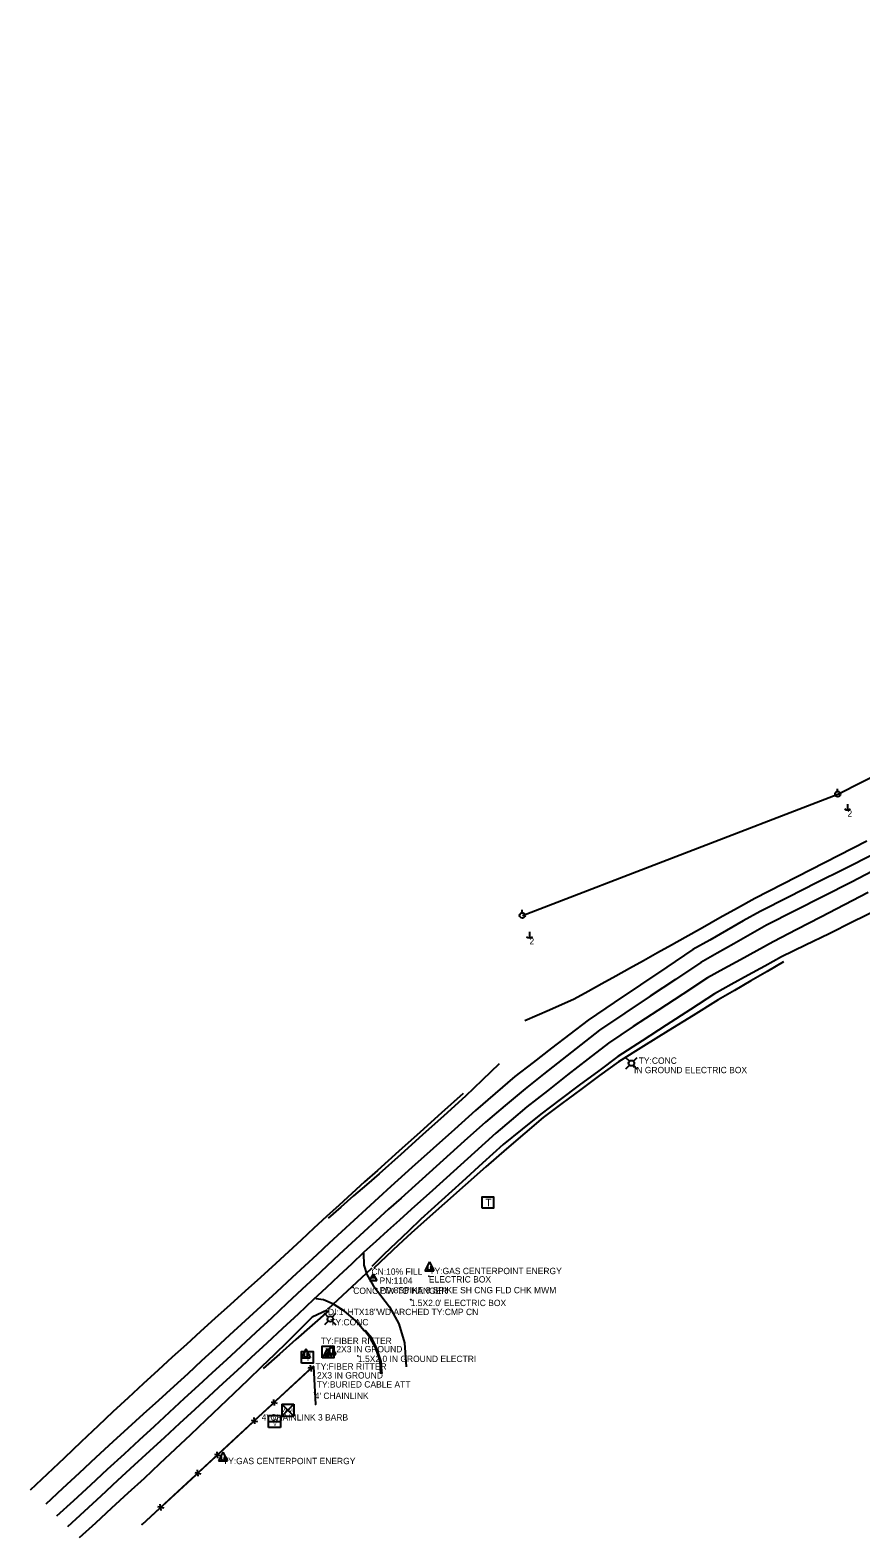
# Model space of a CAD drawing. Extents: x 1707085 to 1720058, y 548761 to 560063.
# Drawn here: x 1710676 to 1711331, y 548761 to 549950 of the extents above; entities that cross this region are included whole.
import ezdxf

# ---------------------------------------------------------------- set-up
doc = ezdxf.new("R2010")
doc.units = 0
for name, color, linetype in [('3', 7, 'Continuous'), ('R_Contours', 7, 'Continuous'), ('R_Draft', 7, 'Continuous'), ('R_Water Annot', 7, 'Continuous'), ('S_CURB', 7, 'Continuous'), ('S_DRG_PT_SYM', 7, 'Continuous'), ('S_DRIVEWAY', 7, 'Continuous'), ('S_EDGE_PAVEMENT', 7, 'Continuous'), ('S_MISC_STRUCTURES_ANNOT', 7, 'Continuous'), ('S_MSC_PT_SYM', 7, 'Continuous'), ('S_PAVEMENT_CROWN', 7, 'Continuous'), ('S_SECONDARY_CTL_ANNOT', 7, 'Continuous'), ('S_SIDE_DRAIN_ANNOT', 7, 'Continuous'), ('S_SURVEY_TEXT_ANNOT', 7, 'Continuous'), ('S_TELEPHONE_UTILITIES', 7, 'Continuous'), ('S_TELEPHONE_UTILITIES_ANNOT', 7, 'Continuous'), ('S_UNDERGROUND_CABLE', 7, 'Continuous'), ('S_UTILITY_POLE', 7, 'Continuous'), ('S_UTILITY_POLE_ANNOT', 7, 'Continuous')]:
    doc.layers.add(name, color=color, linetype=linetype)

msp = doc.modelspace()

# ---------------------------------------------------------------- linework, layer by layer
for points in [[(1711335.9, 549310.1), (1711313.8, 549298.8), (1711291.7, 549287.6), (1711269.7, 549276.4), (1711247.6, 549265.1), (1711233.9, 549257.4), (1711220.2, 549249.7), (1711206.5, 549241.9), (1711192.8, 549234.2), (1711181.9, 549228.2), (1711170.9, 549222.1), (1711160, 549216), (1711149, 549209.9), (1711138.1, 549203.9), (1711127.1, 549197.8), (1711116.2, 549191.7), (1711105.2, 549185.6), (1711085.8, 549177.1), (1711066.4, 549168.6)], [(1711343.8, 549255.7), (1711325, 549246.5), (1711306.3, 549237.3), (1711287.5, 549228.2), (1711268.8, 549219), (1711255.5, 549211.7), (1711242.3, 549204.5), (1711229.1, 549197.2), (1711215.9, 549190), (1711196.9, 549177.6), (1711177.8, 549165.2), (1711158.8, 549152.8), (1711139.8, 549140.5), (1711124.6, 549129.1), (1711109.3, 549117.8), (1711094.1, 549106.5), (1711078.9, 549095.1), (1711064.2, 549083.1), (1711049.4, 549071), (1711033.1, 549056.3), (1711016.9, 549041.6), (1711000.6, 549026.9), (1710984.4, 549012.2), (1710974.7, 549002.9), (1710965, 548993.6), (1710955.3, 548984.3), (1710945.7, 548975)], [(1711270.3, 549215.1), (1711257.4, 549207.6), (1711244.5, 549200.1), (1711231.7, 549192.6), (1711218.8, 549185.1), (1711199.1, 549172.9), (1711179.4, 549160.7), (1711159.8, 549148.5), (1711140.1, 549136.3), (1711125.2, 549125.4), (1711110.4, 549114.4), (1711095.5, 549103.5), (1711080.7, 549092.5), (1711066.3, 549080.1), (1711051.9, 549067.7), (1711035.6, 549053.4), (1711019.3, 549039), (1711003, 549024.6), (1710986.7, 549010.2), (1710976.8, 549001.1), (1710966.9, 548992), (1710957.1, 548982.8), (1710947.2, 548973.7)], [(1711046, 549134.6), (1711032.8, 549121.8), (1711019.5, 549109.1), (1711002.5, 549093.8), (1710985.6, 549078.6), (1710968.6, 549063.3), (1710951.6, 549048.1), (1710941.5, 549039.3), (1710931.4, 549030.5), (1710921.3, 549021.7), (1710911.2, 549012.9)], [(1711017.7, 549111.2), (1711000.8, 549096.1), (1710983.9, 549080.9), (1710967, 549065.8), (1710950.1, 549050.6), (1710940.1, 549041.6), (1710930, 549032.5), (1710920, 549023.4), (1710910, 549014.4), (1710900, 549005.1), (1710890, 548995.8), (1710880, 548986.5), (1710870, 548977.2), (1710858, 548966.3), (1710846, 548955.5), (1710834, 548944.7), (1710822, 548933.8), (1710810.8, 548923.7), (1710799.6, 548913.5), (1710788.4, 548903.4), (1710777.3, 548893.3), (1710765.4, 548882.3), (1710753.6, 548871.3), (1710741.7, 548860.3), (1710729.9, 548849.3), (1710716.5, 548836.6), (1710703.2, 548823.9), (1710689.8, 548811.2), (1710676.4, 548798.5)], [(1710910.5, 548940.6), (1710898.8, 548935), (1710888.9, 548925.2), (1710878.9, 548915.3), (1710868.9, 548905.5), (1710858.9, 548895.7), (1710847.9, 548885.2), (1710836.9, 548874.7), (1710826, 548864.2), (1710815, 548853.7), (1710802.8, 548842.2), (1710790.6, 548830.8), (1710778.4, 548819.3), (1710766.3, 548807.9), (1710753.4, 548796.2), (1710740.6, 548784.4), (1710727.8, 548772.7), (1710715, 548761)], [(1710911.7, 548940.1), (1710898.8, 548928.7), (1710885.9, 548917.3), (1710873, 548905.8), (1710860.1, 548894.4)]]:
    msp.add_lwpolyline(points)
at = {"layer": '3'}
msp.add_line((1710911.2, 548941.6), (1710945.5, 548973.4), dxfattribs=at)
at = {"layer": 'R_Contours'}
for p, q in [((1710764.8, 548771.6), (1710898.8, 548895.6)), ((1710895.4, 548895.2), (1710900.3, 548894.2)), ((1710898.2, 548892.2), (1710897.5, 548897.2)), ((1710899.7, 548896.2), (1710901.4, 548866.1)), ((1710866.3, 548868.3), (1710871.2, 548867.2)), ((1710869.1, 548865.3), (1710868.4, 548870.2)), ((1710850.7, 548853.9), (1710855.6, 548852.8)), ((1710853.5, 548850.9), (1710852.9, 548855.8)), ((1710821.6, 548826.9), (1710826.5, 548825.9)), ((1710824.4, 548823.9), (1710823.7, 548828.9)), ((1710806.1, 548812.6), (1710811, 548811.5)), ((1710808.9, 548809.6), (1710808.2, 548814.5)), ((1710776.9, 548785.6), (1710781.8, 548784.6)), ((1710779.7, 548782.6), (1710779, 548787.6))]:
    msp.add_line(p, q, dxfattribs=at)
for points in [[(1710870, 548869), (1710896.5, 548893.5)], [(1710899.7, 548896.2), (1710901.4, 548866.1)], [(1710854.1, 548854.3), (1710867.4, 548866.5)], [(1710825.4, 548827.6), (1710851.9, 548852.1)], [(1710809.5, 548812.9), (1710822.7, 548825.2)], [(1710780.7, 548786.3), (1710807.2, 548810.8)], [(1710764.8, 548771.6), (1710778, 548783.9)]]:
    msp.add_lwpolyline(points, dxfattribs=at)
at = {"layer": 'R_Draft'}
for p, q in [((1710946.8, 548968.9), (1710943.8, 548964)), ((1710943.8, 548964), (1710949.8, 548964)), ((1710946.8, 548968.9), (1710949.8, 548964))]:
    msp.add_line(p, q, dxfattribs=at)
for radius in [0.311, 0.183, 0.103]:
    msp.add_circle((1710946.8, 548966.3), radius, dxfattribs=at)
at = {"layer": 'R_Water Annot'}
for p, q in [((1710874.8, 548866.4), (1710884.2, 548866.4)), ((1710874.8, 548866.4), (1710874.8, 548856.9)), ((1710874.8, 548866.4), (1710884.2, 548856.9)), ((1710884.2, 548866.4), (1710874.8, 548856.9)), ((1710884.2, 548866.4), (1710884.2, 548856.9)), ((1710864.3, 548857.5), (1710873.7, 548857.5)), ((1710864.3, 548848.1), (1710864.3, 548857.5)), ((1710864.3, 548852.8), (1710873.7, 548852.8)), ((1710873.7, 548857.5), (1710873.7, 548848.1)), ((1710874.8, 548856.9), (1710884.2, 548856.9)), ((1710873.7, 548848.1), (1710864.3, 548848.1))]:
    msp.add_line(p, q, dxfattribs=at)
at = {"layer": 'S_CURB'}
msp.add_lwpolyline([(1710952.9, 548890.3), (1710952.2, 548900.2), (1710948.9, 548910.5), (1710944.6, 548918.1), (1710940.8, 548923.3), (1710940, 548924.1), (1710940.6, 548924.3), (1710941.2, 548923.4), (1710945.2, 548918.6), (1710949.2, 548911), (1710952.8, 548900.1), (1710953.3, 548892.1)], dxfattribs=at)
at = {"layer": 'S_DRG_PT_SYM'}
for points in [[(1710945.5, 548973.4), (1710945.5, 548973.4), (1710945.5, 548973.4), (1710945.4, 548973.4), (1710945.5, 548973.4), (1710945.5, 548973.3), (1710945.5, 548973.4), (1710945.5, 548973.4)], [(1710911.2, 548941.6), (1710911.2, 548941.7), (1710911.2, 548941.6), (1710911.2, 548941.6), (1710911.2, 548941.6), (1710911.2, 548941.6), (1710911.2, 548941.6), (1710911.3, 548941.6)]]:
    msp.add_lwpolyline(points, dxfattribs=at)
at = {"layer": 'S_DRIVEWAY'}
for points in [[(1710939.3, 548985.3), (1710939.5, 548975.9), (1710941.8, 548968.7), (1710946.9, 548960), (1710959.7, 548943.2), (1710967.1, 548929.8), (1710971.6, 548914.7), (1710972.8, 548895.8)], [(1710953.9, 548890.5), (1710952.7, 548900.3), (1710949.5, 548910.7), (1710945.7, 548918.3), (1710940.8, 548924.3), (1710939.8, 548924.1), (1710932.8, 548932.3), (1710924.1, 548939.6), (1710915.6, 548945.3), (1710907.7, 548948.6), (1710901.5, 548949.3)]]:
    msp.add_lwpolyline(points, dxfattribs=at)
at = {"layer": 'S_EDGE_PAVEMENT'}
for points in [[(1711340.9, 549299.8), (1711318.7, 549288.5), (1711296.4, 549277.3), (1711274.1, 549266), (1711251.8, 549254.8), (1711238.6, 549247.3), (1711225.4, 549239.8), (1711212.1, 549232.3), (1711198.9, 549224.8), (1711178.2, 549210.9), (1711157.6, 549197), (1711136.9, 549183.1), (1711116.3, 549169.2), (1711101.9, 549158.1), (1711087.4, 549147), (1711073, 549135.8), (1711058.6, 549124.7), (1711043.1, 549111.3), (1711027.5, 549098), (1711010.8, 549083), (1710994.1, 549068), (1710977.4, 549053), (1710960.7, 549038), (1710951, 549029.1), (1710941.3, 549020.1), (1710931.5, 549011.2), (1710921.8, 549002.2), (1710912.1, 548993.2), (1710902.4, 548984.2), (1710892.7, 548975.2), (1710883, 548966.2), (1710870.6, 548954.8), (1710858.3, 548943.4), (1710845.9, 548932.1), (1710833.6, 548920.7), (1710822.6, 548910.6), (1710811.6, 548900.5), (1710800.7, 548890.4), (1710789.7, 548880.3), (1710777.6, 548869.4), (1710765.6, 548858.4), (1710753.5, 548847.5), (1710741.5, 548836.6), (1710728.3, 548824.3), (1710715.1, 548812), (1710701.9, 548799.8), (1710688.7, 548787.5)], [(1711337.1, 549269.7), (1711318.4, 549260), (1711299.7, 549250.3), (1711280.9, 549240.6), (1711262.2, 549230.9), (1711249.2, 549223.8), (1711236.3, 549216.7), (1711223.3, 549209.6), (1711210.3, 549202.5), (1711190.8, 549189.6), (1711171.3, 549176.8), (1711151.8, 549164), (1711132.3, 549151.1), (1711116.2, 549138.6), (1711100.1, 549126), (1711084.1, 549113.5), (1711068, 549100.9), (1711055.7, 549090.4), (1711043.5, 549079.9), (1711026.8, 549064.9), (1711010.1, 549049.9), (1710993.5, 549034.9), (1710976.8, 549019.9), (1710967.5, 549011.4), (1710958.2, 549003), (1710948.8, 548994.6), (1710939.5, 548986.2), (1710929.6, 548976.8), (1710919.7, 548967.5), (1710909.8, 548958.2), (1710899.9, 548948.8), (1710887.6, 548937.4), (1710875.3, 548926), (1710862.9, 548914.6), (1710850.6, 548903.2), (1710839.5, 548893), (1710828.4, 548882.7), (1710817.3, 548872.5), (1710806.2, 548862.2), (1710794.2, 548851.2), (1710782.3, 548840.2), (1710770.4, 548829.3), (1710758.5, 548818.3), (1710745.3, 548806.1), (1710732.2, 548793.9), (1710719.1, 548781.8), (1710705.9, 548769.6)]]:
    msp.add_lwpolyline(points, dxfattribs=at)
at = {"layer": 'S_MSC_PT_SYM'}
for points in [[(1711152.4, 549132.3), (1711152.4, 549132.4), (1711152.4, 549132.3), (1711152.4, 549132.3), (1711152.4, 549132.3), (1711152.4, 549132.3), (1711152.4, 549132.3), (1711152.5, 549132.3)], [(1710931.1, 548958.3), (1710931.1, 548958.4), (1710931.1, 548958.3), (1710931.1, 548958.3), (1710931.1, 548958.3), (1710931.1, 548958.3), (1710931.1, 548958.3), (1710931.2, 548958.3)], [(1710990.7, 548967.3), (1710990.7, 548967.4), (1710990.7, 548967.3), (1710990.6, 548967.3), (1710990.7, 548967.3), (1710990.7, 548967.3), (1710990.7, 548967.3), (1710990.7, 548967.3)], [(1710976.4, 548948.7), (1710976.4, 548948.8), (1710976.4, 548948.7), (1710976.4, 548948.7), (1710976.4, 548948.7), (1710976.4, 548948.7), (1710976.4, 548948.7), (1710976.5, 548948.7)], [(1710934.8, 548904.6), (1710934.8, 548904.6), (1710934.8, 548904.6), (1710934.8, 548904.6), (1710934.8, 548904.6), (1710934.8, 548904.5), (1710934.8, 548904.6), (1710934.9, 548904.6)], [(1710898.8, 548895.6), (1710898.8, 548895.6), (1710898.8, 548895.6), (1710898.8, 548895.6), (1710898.8, 548895.6), (1710898.8, 548895.5), (1710898.8, 548895.6), (1710898.9, 548895.6)], [(1710899.7, 548896.2), (1710899.7, 548896.2), (1710899.7, 548896.2), (1710899.6, 548896.2), (1710899.7, 548896.2), (1710899.7, 548896.1), (1710899.7, 548896.2), (1710899.7, 548896.2)], [(1710900.7, 548875.5), (1710900.7, 548875.5), (1710900.7, 548875.5), (1710900.6, 548875.5), (1710900.7, 548875.5), (1710900.7, 548875.4), (1710900.7, 548875.5), (1710900.7, 548875.5)], [(1710901.4, 548866.1), (1710901.4, 548866.2), (1710901.4, 548866.1), (1710901.3, 548866.1), (1710901.4, 548866.1), (1710901.4, 548866.1), (1710901.4, 548866.1), (1710901.4, 548866.1)], [(1710858.9, 548858.5), (1710858.9, 548858.5), (1710858.9, 548858.5), (1710858.9, 548858.5), (1710858.9, 548858.5), (1710858.9, 548858.4), (1710858.9, 548858.5), (1710859, 548858.5)], [(1710764.8, 548771.6), (1710764.8, 548771.7), (1710764.8, 548771.6), (1710764.7, 548771.6), (1710764.8, 548771.6), (1710764.8, 548771.6), (1710764.8, 548771.6), (1710764.8, 548771.6)]]:
    msp.add_lwpolyline(points, dxfattribs=at)
at = {"layer": 'S_PAVEMENT_CROWN'}
msp.add_lwpolyline([(1711346, 549289.4), (1711323.8, 549278), (1711301.5, 549266.7), (1711279.2, 549255.3), (1711256.9, 549243.9), (1711244, 549236.6), (1711231, 549229.3), (1711218.1, 549222), (1711205.1, 549214.6), (1711185.1, 549201.3), (1711165.2, 549187.9), (1711145.2, 549174.5), (1711125.2, 549161.1), (1711110.5, 549149.6), (1711095.9, 549138), (1711081.2, 549126.5), (1711066.5, 549114.9), (1711050.9, 549101.9), (1711035.3, 549088.8), (1711018.6, 549073.8), (1711002, 549058.8), (1710985.4, 549043.8), (1710968.8, 549028.8), (1710959, 549020), (1710949.3, 549011.1), (1710939.5, 549002.2), (1710929.8, 548993.4), (1710920.1, 548984.3), (1710910.4, 548975.2), (1710900.6, 548966.1), (1710890.9, 548957.1), (1710878.7, 548945.7), (1710866.6, 548934.3), (1710854.4, 548923), (1710842.2, 548911.6), (1710831.1, 548901.4), (1710820, 548891.2), (1710809, 548881), (1710797.9, 548870.8), (1710786, 548859.8), (1710774.2, 548848.9), (1710762.3, 548838), (1710750.5, 548827.1), (1710737.2, 548814.8), (1710723.9, 548802.5), (1710710.6, 548790.3), (1710697.3, 548778)], dxfattribs=at)
at = {"layer": 'S_TELEPHONE_UTILITIES'}
for points in [[(1711032.6, 549020.9), (1711032.6, 549029.9), (1711041.6, 549029.9), (1711041.6, 549020.9)], [(1710906.7, 548903), (1710906.7, 548912), (1710915.7, 548912), (1710915.7, 548903)], [(1710890.4, 548898.8), (1710890.4, 548907.8), (1710899.4, 548907.8), (1710899.4, 548898.8)]]:
    msp.add_lwpolyline(points, close=True, dxfattribs=at)
at = {"layer": 'S_UNDERGROUND_CABLE'}
for p, q in [((1710991.1, 548978.5), (1710987.5, 548971.4)), ((1710987.5, 548971.4), (1710994.5, 548971.4)), ((1710989.8, 548972.6), (1710989.8, 548975.1)), ((1710990.5, 548972), (1710989.8, 548972.6)), ((1710991.7, 548972), (1710990.5, 548972)), ((1710991.1, 548978.5), (1710994.5, 548971.4)), ((1710992.2, 548972.6), (1710991.7, 548972)), ((1710992.2, 548975.1), (1710992.2, 548972.6)), ((1710893.7, 548910.1), (1710890.2, 548903)), ((1710893.7, 548910.1), (1710897.2, 548903)), ((1710910.6, 548910.2), (1710907, 548903.1)), ((1710913.8, 548912.7), (1710910.3, 548905.6)), ((1710910.6, 548910.2), (1710914.1, 548903.1)), ((1710913.8, 548912.7), (1710917.3, 548905.6)), ((1710890.2, 548903), (1710897.2, 548903)), ((1710892.5, 548904.3), (1710892.5, 548906.7)), ((1710893.2, 548903.6), (1710892.5, 548904.3)), ((1710894.4, 548903.6), (1710893.2, 548903.6)), ((1710894.9, 548904.3), (1710894.4, 548903.6)), ((1710894.9, 548906.7), (1710894.9, 548904.3)), ((1710907, 548903.1), (1710914.1, 548903.1)), ((1710909.4, 548904.3), (1710909.4, 548906.8)), ((1710910, 548903.7), (1710909.4, 548904.3)), ((1710911.2, 548903.7), (1710910, 548903.7)), ((1710910.3, 548905.6), (1710917.3, 548905.6)), ((1710911.7, 548904.3), (1710911.2, 548903.7)), ((1710911.7, 548906.8), (1710911.7, 548904.3)), ((1710912.6, 548906.9), (1710912.6, 548909.3)), ((1710913.3, 548906.2), (1710912.6, 548906.9)), ((1710914.5, 548906.2), (1710913.3, 548906.2)), ((1710915, 548906.9), (1710914.5, 548906.2)), ((1710915, 548909.3), (1710915, 548906.9)), ((1710828.4, 548828.6), (1710824.9, 548821.6)), ((1710828.4, 548828.6), (1710831.9, 548821.6)), ((1710824.9, 548821.6), (1710831.9, 548821.6)), ((1710827.2, 548822.8), (1710827.2, 548825.2)), ((1710827.8, 548822.1), (1710827.2, 548822.8)), ((1710829, 548822.1), (1710827.8, 548822.1)), ((1710829.5, 548822.8), (1710829, 548822.1)), ((1710829.5, 548825.2), (1710829.5, 548822.8))]:
    msp.add_line(p, q, dxfattribs=at)
at = {"layer": 'S_UTILITY_POLE'}
for p, q in [((1711312.9, 549349.5), (1711312.9, 549351.6)), ((1711320.7, 549339.4), (1711320.7, 549334.7)), ((1711064.3, 549253.9), (1711064.3, 549256)), ((1711070, 549238.7), (1711070, 549234)), ((1711148.8, 549136.7), (1711145.8, 549139.7)), ((1711152, 549136.7), (1711155, 549139.7)), ((1711148.8, 549133.6), (1711145.8, 549130.6)), ((1711152, 549133.6), (1711155, 549130.6)), ((1710911.4, 548935.1), (1710908.4, 548938.1)), ((1710914.5, 548935.1), (1710917.5, 548938.1)), ((1710911.4, 548931.9), (1710908.4, 548928.9)), ((1710914.5, 548931.9), (1710917.5, 548928.9))]:
    msp.add_line(p, q, dxfattribs=at)
msp.add_lwpolyline([(1711064.4, 549251.7), (1711313, 549347.3), (1711526.7, 549455.5), (1711746.3, 549567), (1712411.7, 549904.8), (1712500.9, 549949.6)], dxfattribs=at)
for centre, radius in [((1711313, 549347.3), 2.13), ((1711064.4, 549251.7), 2.13), ((1711150.4, 549135.2), 2.21), ((1710913, 548933.5), 2.21)]:
    msp.add_circle(centre, radius, dxfattribs=at)
for centre in [(1711320.8, 549338.1), (1711070, 549237.4)]:
    msp.add_arc(centre, 3.41, 226.3972, 313.6028, dxfattribs=at)

# ---------------------------------------------------------------- texts
at = {"layer": 'R_Draft'}
msp.add_text('TV', height=1.5, rotation=360, dxfattribs=at).set_placement((1710945.6, 548964.3))
at = {"layer": 'R_Water Annot'}
for s, p in [('W M', (1710875, 548860.1)), ('W', (1710867.8, 548853.4)), ('V', (1710868, 548849.3))]:
    msp.add_text(s, height=3, rotation=360, dxfattribs=at).set_placement(p)
at = {"layer": 'S_MISC_STRUCTURES_ANNOT'}
for s, p in [('IN GROUND ELECTRIC BOX', (1711152.4, 549127.3)), ('ELECTRIC BOX', (1710990.7, 548962.3)), ("1.5X2.0' ELECTRIC BOX", (1710976.4, 548943.7)), ('1.5X2.0 IN GROUND ELECTRI', (1710934.8, 548899.6))]:
    msp.add_text(s, height=5, dxfattribs=at).set_placement(p)
at = {"layer": 'S_SECONDARY_CTL_ANNOT'}
for s, p in [('PN:1104', (1710951.8, 548961.3)), ('PD:8SPIKE 8 SPIKE SH CNG FLD CHK MWM', (1710951.8, 548953.8))]:
    msp.add_text(s, height=5, dxfattribs=at).set_placement(p)
at = {"layer": 'S_SIDE_DRAIN_ANNOT'}
for s, p in [('CN:10% FILL', (1710945.5, 548968.4)), ('DI:1\' HTX18"WD ARCHED TY:CMP CN', (1710911.2, 548936.6))]:
    msp.add_text(s, height=5, dxfattribs=at).set_placement(p)
at = {"layer": 'S_SURVEY_TEXT_ANNOT'}
for s, p in [('CONC DW TO HANGER', (1710931.1, 548953.3)), ("4' CHAINLINK", (1710900.7, 548870.5)), ("4' CHAINLINK 3 BARB", (1710858.9, 548853.5))]:
    msp.add_text(s, height=5, dxfattribs=at).set_placement(p)
at = {"layer": 'S_TELEPHONE_UTILITIES'}
for p in [(1711035.2, 549022.4), (1710909.3, 548904.5), (1710893, 548900.3)]:
    msp.add_text('T', height=6, rotation=360, dxfattribs=at).set_placement(p)
at = {"layer": 'S_TELEPHONE_UTILITIES_ANNOT'}
for p in [(1710917.8, 548907.3), (1710902.5, 548886.6)]:
    msp.add_text('2X3 IN GROUND', height=5, dxfattribs=at).set_placement(p)
at = {"layer": 'S_UTILITY_POLE_ANNOT'}
for s, p in [('2', (1711320.7, 549329.5)), ('2', (1711070, 549228.8)), ('TY:CONC', (1711156.1, 549134.7)), ('TY:GAS CENTERPOINT ENERGY', (1710991.1, 548968.9)), ('TY:CONC', (1710913, 548928.5)), ('TY:FIBER RITTER', (1710905.4, 548913.8)), ('TY:FIBER RITTER', (1710901.3, 548893.6)), ('TY:BURIED CABLE ATT', (1710902.3, 548879.5)), ('TY:GAS CENTERPOINT ENERGY', (1710828.4, 548819.1))]:
    msp.add_text(s, height=5, dxfattribs=at).set_placement(p)

doc.saveas('drawing.dxf')
